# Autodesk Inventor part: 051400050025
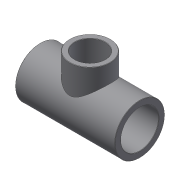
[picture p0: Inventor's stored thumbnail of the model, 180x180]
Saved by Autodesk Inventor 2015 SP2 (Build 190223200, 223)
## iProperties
Created: 2017-10
Part Number: 051400050025
Material: Generic
Description: PLASSON REDUCER TEE - CEMENT PVC 50-25-50
Document SubType Name: Modeling
Designer: KIM
Density: 1 g/cm^3
Appearance: Default
Author: KIM
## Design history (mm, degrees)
derived "051400.ipt"
feature "Solid1::051400.ipt"
feature "Solid2::051400.ipt"
tag "TaggingFeature1"
body "Solid1"
other parameters: "d0" = 118, "d1" = 62, "d2" = 31, "d7" = 0.5, "d8" = 31, "d9" = 46, "d10" = 37, "d11" = 25, "d12" = 22.5, "d23" = 24, "d24" = 0.5, "d26" = 0, "d30" = 0, "d32" = 0, "E_" = 62, "H_" = 118, "l_" = 31, "Z_" = 14, "E_1" = 37, "l_1" = 24, "Z_1" = 12.5, "H_1" = 77, "d_1" = 25
